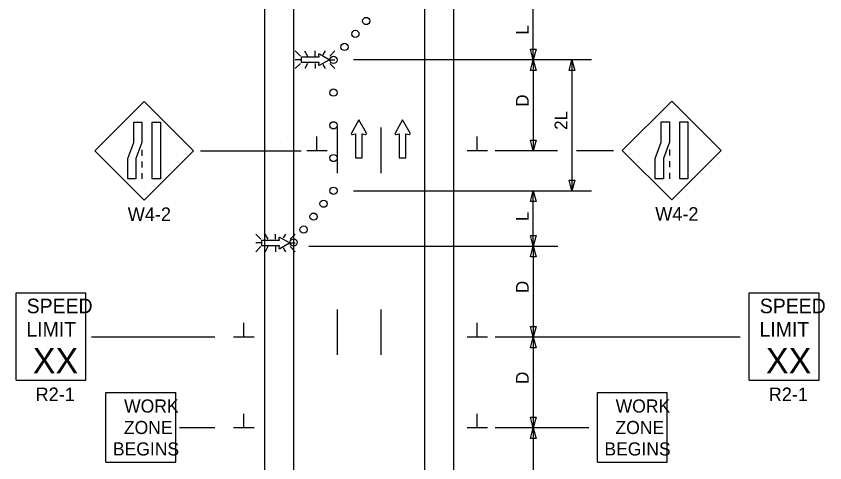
# Model space of a CAD drawing. Extents: x 16724 to 19508, y 5703 to 6974.
# Drawn here: x 17764.2 to 18209.5, y 6436.2 to 6682 of the extents above; entities that cross this region are included whole.
import ezdxf

# ---------------------------------------------------------------- set-up
doc = ezdxf.new("R2010")
doc.units = 0
for name, color, linetype in [('ALI_LEGAL_EX', 7, 'Continuous'), ('BORDER', 7, 'Continuous'), ('MT_SCRATCH_LEVEL_E', 7, 'Continuous'), ('PAVT_EDGE_EX', 7, 'Continuous'), ('TRAFFIC_SIGNS_PR', 7, 'Continuous'), ('TYPICAL_TEXT_DIMEN_PR', 7, 'Continuous')]:
    doc.layers.add(name, color=color, linetype=linetype)

msp = doc.modelspace()

# ---------------------------------------------------------------- linework, layer by layer
at = {"layer": 'ALI_LEGAL_EX'}
for points in [[(17940.96, 6620.69), (17940.96, 6595.69)], [(17964.96, 6620.69), (17964.96, 6595.69)], [(17940.96, 6520.69), (17940.96, 6495.69)], [(17964.96, 6520.69), (17964.96, 6495.69)]]:
    msp.add_lwpolyline(points, dxfattribs=at)
at = {"layer": 'BORDER'}
msp.add_line((17909.54, 6612.74), (17909.54, 6612.74), dxfattribs=at)
at = {"layer": 'MT_SCRATCH_LEVEL_E'}
for p, q in [((17952.86, 6624.9), (17948.75, 6617.66)), ((17957.01, 6617.66), (17952.86, 6624.9)), ((17976.91, 6624.9), (17972.8, 6617.66)), ((17981.06, 6617.66), (17976.91, 6624.9)), ((17949.23, 6616.98), (17951.01, 6617.29)), ((17951.01, 6617.29), (17951.01, 6604.03)), ((17954.75, 6604.03), (17954.75, 6617.29)), ((17954.75, 6617.29), (17956.53, 6616.98)), ((17973.28, 6616.98), (17975.06, 6617.29)), ((17975.06, 6617.29), (17975.06, 6604.03)), ((17978.8, 6604.03), (17978.8, 6617.29)), ((17978.8, 6617.29), (17980.58, 6616.98)), ((17951.01, 6604.03), (17954.75, 6604.03)), ((17975.06, 6604.03), (17978.8, 6604.03))]:
    msp.add_line(p, q, dxfattribs=at)
for centre, start, end in [((17949.16, 6617.43), 150.4248, 279.9638), ((17956.6, 6617.43), 260.0362, 29.7731), ((17973.21, 6617.43), 150.4248, 279.9638), ((17980.65, 6617.43), 260.0362, 29.7731)]:
    msp.add_arc(centre, 0.463, start, end, dxfattribs=at)
at = {"layer": 'PAVT_EDGE_EX'}
for p, q in [((17900.96, 6925.33), (17900.96, 6103.04)), ((17916.96, 6925.33), (17916.96, 6103.04)), ((17988.96, 6925.33), (17988.96, 6103.04)), ((18004.96, 6925.33), (18004.96, 6103.04))]:
    msp.add_line(p, q, dxfattribs=at)
at = {"layer": 'TRAFFIC_SIGNS_PR'}
for p, q in [((17920.73, 6660.07), (17917.91, 6662.9)), ((17923.03, 6662.9), (17924.66, 6660.07)), ((17928.82, 6660.07), (17928.82, 6662.9)), ((17934.29, 6662.9), (17933.08, 6660.8)), ((17939.72, 6662.89), (17936.9, 6660.07)), ((17920.73, 6658.04), (17917.91, 6658.04)), ((17936.9, 6658.04), (17939.72, 6658.04)), ((17920.73, 6656.01), (17917.91, 6653.19)), ((17924.68, 6656.01), (17923.05, 6653.19)), ((17928.82, 6656.01), (17928.82, 6653.19)), ((17933, 6655.38), (17934.26, 6653.19)), ((17939.72, 6653.19), (17936.9, 6656.01)), ((17834.69, 6635.15), (17807.51, 6607.96)), ((17861.88, 6607.96), (17834.69, 6635.15)), ((18125.15, 6635.31), (18097.96, 6608.13)), ((18152.34, 6608.13), (18125.15, 6635.31)), ((17807.51, 6607.96), (17834.69, 6580.78)), ((17833.44, 6608.45), (17833.44, 6605.25)), ((17834.69, 6580.78), (17861.88, 6607.96)), ((18097.96, 6608.13), (18125.15, 6580.94)), ((18123.9, 6608.62), (18123.9, 6605.41)), ((18125.15, 6580.94), (18152.34, 6608.13)), ((17833.44, 6602.05), (17833.44, 6598.84)), ((18123.9, 6602.21), (18123.9, 6599)), ((17833.44, 6595.64), (17833.44, 6592.43)), ((18123.9, 6595.8), (18123.9, 6592.6)), ((17898.89, 6559.29), (17896.07, 6562.11)), ((17901.19, 6562.11), (17902.82, 6559.29)), ((17906.98, 6559.29), (17906.98, 6562.11)), ((17912.44, 6562.11), (17911.24, 6560.01)), ((17917.88, 6562.11), (17915.06, 6559.29)), ((17898.89, 6557.26), (17896.07, 6557.26)), ((17898.89, 6555.22), (17896.07, 6552.4)), ((17902.84, 6555.22), (17901.21, 6552.4)), ((17906.98, 6555.22), (17906.98, 6552.4)), ((17911.16, 6554.59), (17912.42, 6552.4)), ((17915.06, 6557.26), (17917.88, 6557.26)), ((17917.88, 6552.4), (17915.06, 6555.22)), ((17764.19, 6529.7), (17802.64, 6529.7)), ((17764.19, 6481.64), (17764.19, 6529.7)), ((17802.64, 6481.64), (17802.64, 6529.7)), ((18167.9, 6529.7), (18206.35, 6529.7)), ((18167.9, 6481.64), (18167.9, 6529.7)), ((18206.35, 6481.64), (18206.35, 6529.7)), ((17764.19, 6481.64), (17802.64, 6481.64)), ((18167.9, 6481.64), (18206.35, 6481.64)), ((17813.63, 6436.53), (17813.63, 6474.93)), ((17813.63, 6474.93), (17852.03, 6474.93)), ((17852.03, 6436.53), (17852.03, 6474.93)), ((18084.3, 6436.53), (18084.3, 6474.93)), ((18084.3, 6474.93), (18122.7, 6474.93)), ((18122.7, 6436.53), (18122.7, 6474.93)), ((17813.63, 6436.53), (17852.03, 6436.53)), ((18084.3, 6436.53), (18122.7, 6436.53))]:
    msp.add_line(p, q, dxfattribs=at)
for points in [[(17930.64, 6660.73), (17930.87, 6659.43), (17921.15, 6659.43), (17921.15, 6656.69), (17930.87, 6656.69), (17930.64, 6655.38)], [(17931.14, 6655.03), (17936.45, 6658.04), (17931.14, 6661.08)], [(17908.8, 6559.94), (17909.03, 6558.64), (17899.31, 6558.64), (17899.31, 6555.9), (17909.03, 6555.9), (17908.8, 6554.59)], [(17909.3, 6554.24), (17914.61, 6557.26), (17909.3, 6560.3)]]:
    msp.add_lwpolyline(points, dxfattribs=at)
for points in [[(17833.44, 6623.72), (17833.44, 6612.52), (17830.09, 6603.63), (17830.09, 6592.43), (17825.6, 6592.43), (17825.6, 6603.63), (17828.94, 6612.52), (17828.94, 6623.72)], [(17843.59, 6623.72), (17843.59, 6592.43), (17839.09, 6592.43), (17839.09, 6623.72)], [(18123.9, 6623.88), (18123.9, 6612.69), (18120.55, 6603.79), (18120.55, 6592.6), (18116.05, 6592.6), (18116.05, 6603.79), (18119.4, 6612.69), (18119.4, 6623.88)], [(18134.05, 6623.88), (18134.05, 6592.6), (18129.55, 6592.6), (18129.55, 6623.88)]]:
    msp.add_lwpolyline(points, close=True, dxfattribs=at)
for centre in [(17956.96, 6679.39), (17950.96, 6672.25), (17944.96, 6665.11), (17938.96, 6657.97), (17938.96, 6639.97), (17938.96, 6621.97), (17938.96, 6603.97), (17938.96, 6585.97), (17933.46, 6578.84), (17927.96, 6571.71), (17922.47, 6564.58), (17916.97, 6557.46)]:
    msp.add_circle(centre, 2, dxfattribs=at)
for centre, start, end in [((17930.98, 6660.78), 61.4833, 189.9593), ((17930.98, 6655.33), 170.7308, 298.8916), ((17909.14, 6560), 61.4833, 189.9593), ((17909.14, 6554.54), 170.7308, 298.8916)]:
    msp.add_arc(centre, 0.341, start, end, dxfattribs=at)
at = {"layer": 'TYPICAL_TEXT_DIMEN_PR'}
for p, q in [((18048.96, 6657.97), (18048.96, 6688.54)), ((18048.96, 6657.97), (18047.39, 6663.83)), ((18047.39, 6663.83), (18048.96, 6663.83)), ((18048.96, 6663.83), (18050.53, 6663.83)), ((18050.53, 6663.83), (18048.96, 6657.97)), ((18081, 6657.97), (17949.86, 6657.97)), ((18047.39, 6652.11), (18048.96, 6657.97)), ((18048.96, 6657.97), (18048.96, 6607.97)), ((18048.96, 6657.97), (18050.53, 6652.11)), ((18068.65, 6652.11), (18070.22, 6657.97)), ((18070.22, 6657.97), (18071.79, 6652.11)), ((18070.22, 6657.97), (18070.22, 6585.97)), ((18048.96, 6652.11), (18047.39, 6652.11)), ((18050.53, 6652.11), (18048.96, 6652.11)), ((18070.22, 6652.11), (18068.65, 6652.11)), ((18071.79, 6652.11), (18070.22, 6652.11)), ((17929.81, 6607.97), (17929.81, 6615.76)), ((18018.08, 6607.97), (18018.08, 6615.76)), ((18048.96, 6607.97), (18047.39, 6613.83)), ((18047.39, 6613.83), (18048.96, 6613.83)), ((18048.96, 6613.83), (18050.53, 6613.83)), ((18050.53, 6613.83), (18048.96, 6607.97)), ((18070.22, 6612.84), (18070.22, 6609.07)), ((17865.72, 6607.97), (17921.15, 6607.97)), ((17935.43, 6607.97), (17924.18, 6607.97)), ((18023.71, 6607.97), (18012.46, 6607.97)), ((18062.31, 6607.97), (18027.96, 6607.97)), ((18093.14, 6607.97), (18072.77, 6607.97)), ((18070.22, 6585.97), (18068.65, 6591.83)), ((18068.65, 6591.83), (18070.22, 6591.83)), ((18070.22, 6591.83), (18071.79, 6591.83)), ((18071.79, 6591.83), (18070.22, 6585.97)), ((17949.86, 6585.97), (18081, 6585.97)), ((18047.39, 6580.11), (18048.96, 6585.97)), ((18048.96, 6555.41), (18048.96, 6585.97)), ((18048.96, 6585.97), (18050.53, 6580.11)), ((18048.96, 6580.11), (18047.39, 6580.11)), ((18050.53, 6580.11), (18048.96, 6580.11)), ((18048.96, 6555.41), (18047.39, 6561.27)), ((18047.39, 6561.27), (18048.96, 6561.27)), ((18048.96, 6561.27), (18050.53, 6561.27)), ((18050.53, 6561.27), (18048.96, 6555.41)), ((17925.35, 6555.41), (18062.54, 6555.41)), ((18047.39, 6549.55), (18048.96, 6555.41)), ((18048.96, 6555.41), (18048.96, 6505.41)), ((18048.96, 6555.41), (18050.53, 6549.55)), ((18048.96, 6549.55), (18047.39, 6549.55)), ((18050.53, 6549.55), (18048.96, 6549.55)), ((17889.56, 6505.41), (17889.56, 6513.19)), ((18018.08, 6505.41), (18018.08, 6513.19)), ((18048.96, 6505.41), (18047.39, 6511.27)), ((18047.39, 6511.27), (18048.96, 6511.27)), ((18048.96, 6511.27), (18050.53, 6511.27)), ((18050.53, 6511.27), (18048.96, 6505.41)), ((17873.64, 6505.41), (17805.63, 6505.41)), ((17895.18, 6505.41), (17883.93, 6505.41)), ((18023.71, 6505.41), (18012.46, 6505.41)), ((18070.38, 6505.41), (18027.96, 6505.41)), ((18047.39, 6499.55), (18048.96, 6505.41)), ((18048.96, 6505.41), (18048.96, 6455.41)), ((18048.96, 6505.41), (18050.53, 6499.55)), ((18162.77, 6505.41), (18070.38, 6505.41)), ((18048.96, 6499.55), (18047.39, 6499.55)), ((18050.53, 6499.55), (18048.96, 6499.55)), ((17889.56, 6455.41), (17889.56, 6463.19)), ((18018.08, 6455.41), (18018.08, 6463.19)), ((18048.96, 6455.41), (18047.39, 6461.27)), ((18047.39, 6461.27), (18048.96, 6461.27)), ((18048.96, 6461.27), (18050.53, 6461.27)), ((18050.53, 6461.27), (18048.96, 6455.41)), ((17873.64, 6455.41), (17854.13, 6455.41)), ((17895.18, 6455.41), (17883.93, 6455.41)), ((18023.71, 6455.41), (18012.46, 6455.41)), ((18071.99, 6455.41), (18027.96, 6455.41)), ((18047.39, 6449.55), (18048.96, 6455.41)), ((18048.96, 6455.41), (18048.96, 6405.41)), ((18048.96, 6455.41), (18050.53, 6449.55)), ((18079.44, 6455.41), (18071.99, 6455.41)), ((18048.96, 6449.55), (18047.39, 6449.55)), ((18050.53, 6449.55), (18048.96, 6449.55))]:
    msp.add_line(p, q, dxfattribs=at)

# ---------------------------------------------------------------- texts
at = {"layer": 'TRAFFIC_SIGNS_PR'}
for s, height, p in [('W4-2', 7.449, (17825.64, 6569.32)), ('W4-2', 7.449, (18116.1, 6569.49)), ('SPEED', 8.01, (17769.97, 6518.55)), ('SPEED', 8.01, (18173.67, 6518.55)), ('LIMIT', 8.01, (17769.81, 6505.73)), ('LIMIT', 8.01, (18173.51, 6505.73)), ('XX', 14.048, (17773.32, 6485.4)), ('XX', 14.048, (18177.02, 6485.4)), ('R2-1', 7.449, (17774.88, 6470.19)), ('R2-1', 7.449, (18178.59, 6470.19)), ('WORK', 7.217, (17823.63, 6463.89)), ('WORK', 7.217, (18094.3, 6463.89)), ('ZONE', 7.217, (17823.52, 6452.08)), ('ZONE', 7.217, (18094.19, 6452.08)), ('BEGINS', 7.217, (17817.44, 6440.27)), ('BEGINS', 7.217, (18088.11, 6440.27))]:
    msp.add_text(s, height=height, dxfattribs=at).set_placement(p)
at = {"layer": 'TYPICAL_TEXT_DIMEN_PR'}
for s, p in [('L', (18046.4, 6671.83)), ('D', (18046.4, 6632.19)), ('2L', (18067.66, 6619.47)), ('L', (18046.4, 6569.26)), ('D', (18046.4, 6529.63)), ('D', (18046.4, 6479.63))]:
    msp.add_text(s, height=7, rotation=90, dxfattribs=at).set_placement(p)

doc.saveas('drawing.dxf')
